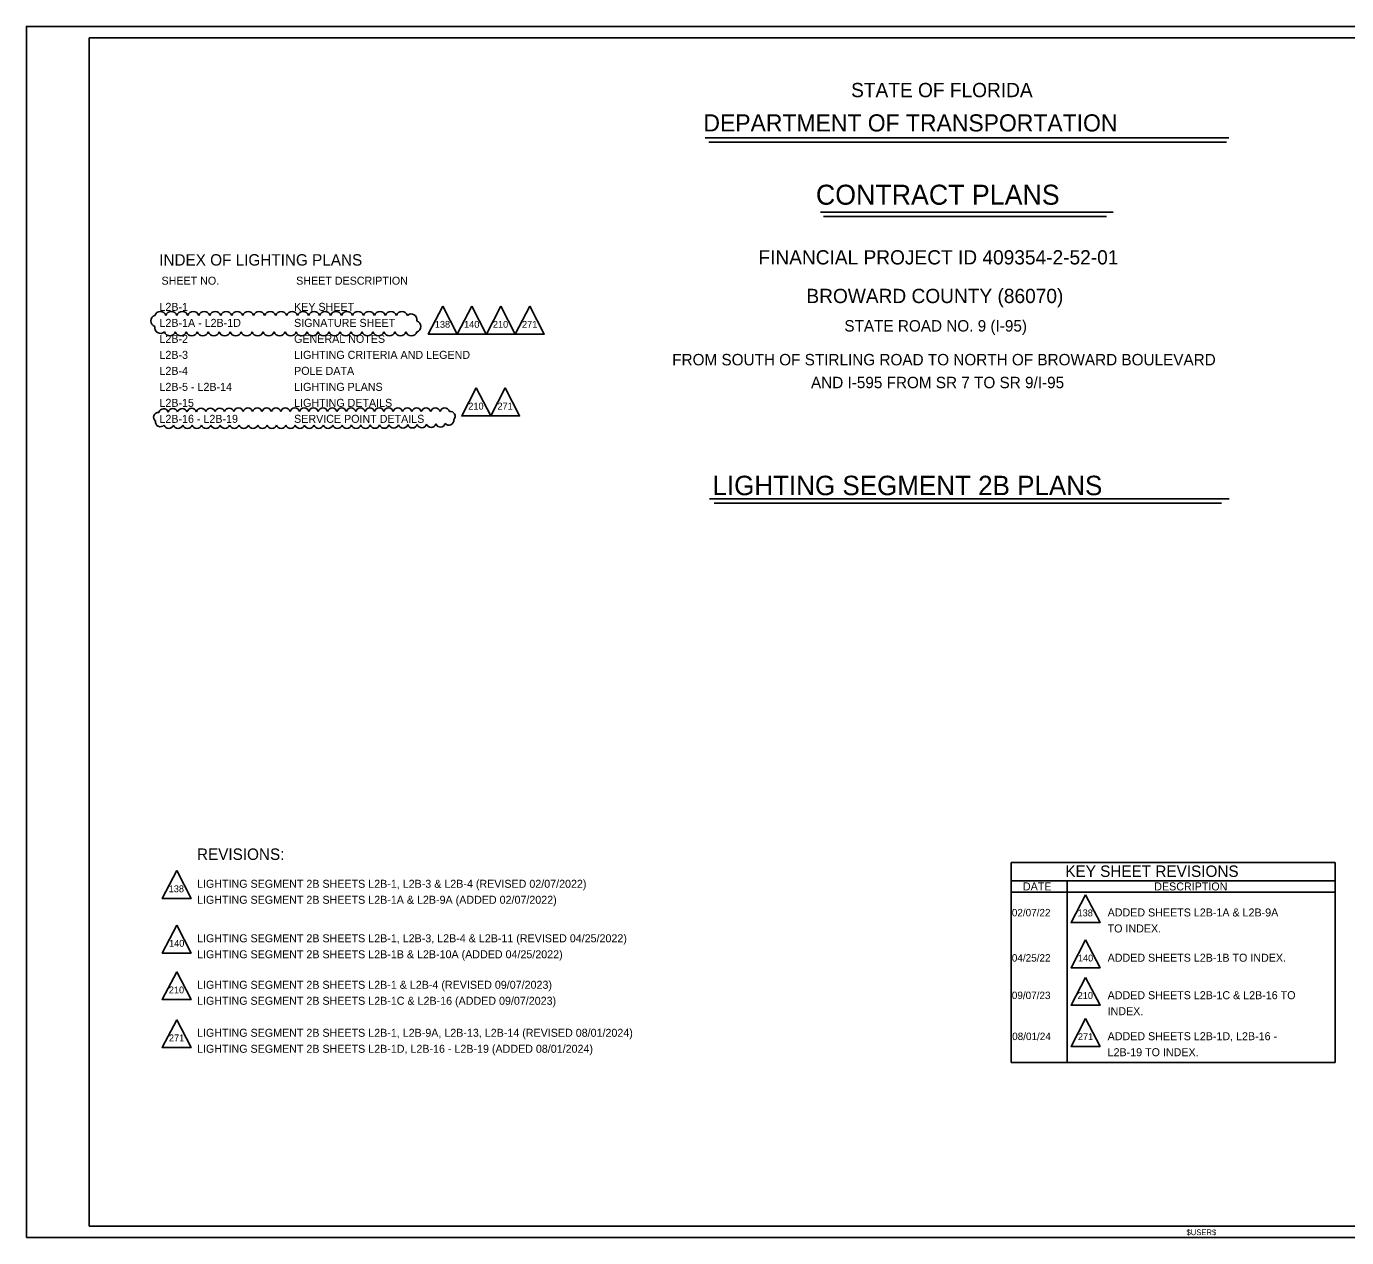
# Model space of a CAD drawing. Extents: x -820.2 to -798.1, y -2199.1 to -2188.5.
# Drawn here: x -820.23 to -808.68, y -2199.12 to -2188.52 of the extents above; entities that cross this region are included whole.
import ezdxf

# ---------------------------------------------------------------- set-up
doc = ezdxf.new("R2010")
doc.units = 0
for name, color, linetype in [('AdhocPoint_dp', 7, 'Continuous'), ('Cloud_dp', 7, 'Continuous'), ('PlotBorder_dp', 7, 'Continuous'), ('SheetBorder_dp', 7, 'Continuous'), ('SumBoxLines_dp', 7, 'Continuous'), ('TextLabel', 7, 'Continuous'), ('TextMinor', 7, 'Continuous'), ('TextNotes', 7, 'Continuous'), ('TextTitle', 7, 'Continuous')]:
    doc.layers.add(name, color=color, linetype=linetype)

msp = doc.modelspace()

# ---------------------------------------------------------------- linework, layer by layer
at = {"layer": 'AdhocPoint_dp'}
msp.add_line((-820.227, -2199.124), (-820.227, -2199.124), dxfattribs=at)
at = {"layer": 'Cloud_dp'}
for points in [[(-816.585, -2190.972), (-816.711, -2191.216), (-816.458, -2191.216)], [(-816.331, -2190.972), (-816.458, -2191.216), (-816.204, -2191.216)], [(-816.077, -2190.972), (-816.203, -2191.216), (-815.95, -2191.216)], [(-815.823, -2190.972), (-815.95, -2191.216), (-815.696, -2191.216)], [(-816.292, -2191.688), (-816.419, -2191.932), (-816.165, -2191.932)], [(-816.038, -2191.688), (-816.165, -2191.932), (-815.912, -2191.932)], [(-818.912, -2195.912), (-819.039, -2196.156), (-818.786, -2196.156)], [(-810.961, -2196.123), (-811.088, -2196.367), (-810.834, -2196.367)], [(-818.912, -2196.389), (-819.039, -2196.633), (-818.786, -2196.633)], [(-810.961, -2196.518), (-811.088, -2196.762), (-810.834, -2196.762)], [(-818.912, -2196.797), (-819.039, -2197.041), (-818.786, -2197.041)], [(-810.961, -2196.846), (-811.088, -2197.09), (-810.834, -2197.09)], [(-818.912, -2197.217), (-819.039, -2197.461), (-818.786, -2197.461)], [(-810.961, -2197.205), (-811.088, -2197.45), (-810.834, -2197.45)]]:
    msp.add_lwpolyline(points, close=True, dxfattribs=at)
for centre, radius, start, end in [((-819.088, -2191.101), 0.0504, 107.5, 252.5), ((-819.055, -2191.068), 0.0504, 17.5, 162.5), ((-818.959, -2191.068), 0.0504, 17.5, 162.5), ((-818.863, -2191.068), 0.0504, 17.5, 162.5), ((-818.767, -2191.068), 0.0504, 17.5, 162.5), ((-818.671, -2191.068), 0.0504, 17.5, 162.5), ((-818.575, -2191.068), 0.0504, 17.5, 162.5), ((-818.479, -2191.068), 0.0504, 17.5, 162.5), ((-818.383, -2191.068), 0.0504, 17.5, 162.5), ((-818.287, -2191.068), 0.0504, 17.5, 162.5), ((-818.191, -2191.068), 0.0504, 17.5, 162.5), ((-818.094, -2191.068), 0.0504, 17.5, 162.5), ((-817.998, -2191.068), 0.0504, 17.5, 162.5), ((-817.902, -2191.068), 0.0504, 17.5, 162.5), ((-817.806, -2191.068), 0.0504, 17.5, 162.5), ((-817.71, -2191.068), 0.0504, 17.5, 162.5), ((-817.614, -2191.068), 0.0504, 17.5, 162.5), ((-817.518, -2191.068), 0.0504, 17.5, 162.5), ((-817.422, -2191.068), 0.0504, 17.5, 162.5), ((-817.326, -2191.068), 0.0504, 17.5, 162.5), ((-817.23, -2191.068), 0.0504, 17.5, 162.5), ((-817.134, -2191.068), 0.0504, 17.5, 162.5), ((-817.038, -2191.068), 0.0504, 17.5, 162.5), ((-816.942, -2191.068), 0.0504, 17.5, 162.5), ((-816.86, -2191.09), 0.0503, 347.2695, 132.2695), ((-819.054, -2191.16), 0.0503, 167.2695, 312.2695), ((-816.826, -2191.15), 0.0504, 287.5, 72.5), ((-818.972, -2191.182), 0.0504, 197.5, 342.5), ((-818.876, -2191.182), 0.0504, 197.5, 342.5), ((-818.78, -2191.182), 0.0504, 197.5, 342.5), ((-818.684, -2191.182), 0.0504, 197.5, 342.5), ((-818.588, -2191.182), 0.0504, 197.5, 342.5), ((-818.492, -2191.182), 0.0504, 197.5, 342.5), ((-818.396, -2191.182), 0.0504, 197.5, 342.5), ((-818.3, -2191.182), 0.0504, 197.5, 342.5), ((-818.204, -2191.182), 0.0504, 197.5, 342.5), ((-818.108, -2191.182), 0.0504, 197.5, 342.5), ((-818.012, -2191.182), 0.0504, 197.5, 342.5), ((-817.915, -2191.182), 0.0504, 197.5, 342.5), ((-817.819, -2191.182), 0.0504, 197.5, 342.5), ((-817.723, -2191.182), 0.0504, 197.5, 342.5), ((-817.627, -2191.182), 0.0504, 197.5, 342.5), ((-817.531, -2191.182), 0.0504, 197.5, 342.5), ((-817.435, -2191.182), 0.0504, 197.5, 342.5), ((-817.339, -2191.182), 0.0504, 197.5, 342.5), ((-817.243, -2191.182), 0.0504, 197.5, 342.5), ((-817.147, -2191.182), 0.0504, 197.5, 342.5), ((-817.051, -2191.182), 0.0504, 197.5, 342.5), ((-816.955, -2191.182), 0.0504, 197.5, 342.5), ((-816.859, -2191.182), 0.0504, 197.5, 342.5), ((-819.027, -2191.913), 0.043, 19.3099, 164.3099), ((-818.945, -2191.911), 0.043, 18.5728, 163.5728), ((-818.863, -2191.91), 0.043, 18.2632, 163.2632), ((-818.781, -2191.909), 0.043, 18.0805, 163.0805), ((-818.699, -2191.908), 0.043, 17.9561, 162.9561), ((-818.617, -2191.907), 0.043, 17.8645, 162.8645), ((-818.535, -2191.907), 0.043, 17.7932, 162.7932), ((-818.453, -2191.907), 0.043, 17.7359, 162.7359), ((-818.371, -2191.906), 0.043, 17.6883, 162.6883), ((-818.289, -2191.906), 0.043, 17.6481, 162.6481), ((-818.207, -2191.906), 0.043, 17.6135, 162.6135), ((-818.125, -2191.906), 0.043, 17.5833, 162.5833), ((-818.043, -2191.906), 0.043, 17.5567, 162.5567), ((-817.961, -2191.906), 0.043, 17.533, 162.533), ((-817.879, -2191.906), 0.043, 17.5117, 162.5117), ((-817.797, -2191.906), 0.043, 17.5001, 162.5001), ((-817.715, -2191.906), 0.043, 17.5, 162.5), ((-817.633, -2191.906), 0.043, 17.5, 162.5), ((-817.551, -2191.906), 0.043, 17.5, 162.5), ((-817.469, -2191.906), 0.043, 17.5, 162.5), ((-817.387, -2191.906), 0.043, 17.5, 162.5), ((-817.305, -2191.906), 0.043, 17.5, 162.5), ((-817.223, -2191.906), 0.043, 17.5, 162.5), ((-817.141, -2191.906), 0.043, 17.5, 162.5), ((-817.059, -2191.906), 0.043, 17.5, 162.5), ((-816.977, -2191.906), 0.043, 17.5, 162.5), ((-816.895, -2191.906), 0.043, 17.5, 162.5), ((-816.813, -2191.906), 0.043, 17.5, 162.5), ((-816.731, -2191.906), 0.043, 17.5, 162.5), ((-816.649, -2191.906), 0.043, 17.5, 162.5), ((-816.567, -2191.906), 0.043, 17.5, 162.5), ((-819.071, -2191.944), 0.0429, 86.8577, 231.8577), ((-819.055, -2191.984), 0.043, 172.6222, 317.6222), ((-816.531, -2191.97), 0.043, 221.9316, 6.9316), ((-816.519, -2191.935), 0.043, 315.2071, 100.2071), ((-818.982, -2192), 0.043, 197.5, 342.5), ((-818.9, -2192), 0.043, 197.5, 342.5), ((-818.818, -2192), 0.043, 197.5, 342.5), ((-818.736, -2192), 0.043, 197.5, 342.5), ((-818.654, -2192), 0.043, 197.5, 342.5), ((-818.572, -2192), 0.043, 197.5, 342.5), ((-818.49, -2192), 0.043, 197.5, 342.5), ((-818.408, -2192), 0.043, 197.5, 342.5), ((-818.326, -2192), 0.043, 197.5, 342.5), ((-818.244, -2192), 0.043, 197.5, 342.5), ((-818.162, -2192), 0.043, 197.5, 342.5), ((-818.08, -2192), 0.043, 197.5, 342.5), ((-817.998, -2192), 0.043, 197.5, 342.5), ((-817.916, -2192), 0.043, 197.5, 342.5), ((-817.834, -2192), 0.043, 197.5, 342.5), ((-817.752, -2192), 0.043, 197.507, 342.507), ((-817.67, -2192), 0.043, 197.5411, 342.5411), ((-817.588, -2192), 0.043, 197.5814, 342.5814), ((-817.506, -2192), 0.043, 197.6265, 342.6265), ((-817.424, -2191.999), 0.043, 197.6774, 342.6774), ((-817.342, -2191.999), 0.043, 197.7355, 342.7355), ((-817.26, -2191.999), 0.043, 197.8027, 342.8027), ((-817.178, -2191.998), 0.043, 197.8816, 342.8816), ((-817.096, -2191.998), 0.043, 197.976, 342.976), ((-817.014, -2191.997), 0.043, 198.0918, 343.0918), ((-816.932, -2191.996), 0.043, 198.2386, 343.2386), ((-816.85, -2191.995), 0.043, 198.4333, 343.4333), ((-816.768, -2191.993), 0.043, 198.7095, 343.7095), ((-816.686, -2191.991), 0.043, 199.1475, 344.1475), ((-816.604, -2191.988), 0.043, 200.0205, 345.0205)]:
    msp.add_arc(centre, radius, start, end, dxfattribs=at)
at = {"layer": 'PlotBorder_dp'}
msp.add_lwpolyline([(-820.227, -2199.124), (-803.727, -2199.124), (-803.727, -2188.524), (-820.227, -2188.524)], close=True, dxfattribs=at)
at = {"layer": 'SheetBorder_dp'}
for p, q in [((-819.677, -2188.624), (-819.677, -2199.024)), ((-819.677, -2188.624), (-804.277, -2188.624)), ((-819.677, -2199.024), (-804.277, -2199.024))]:
    msp.add_line(p, q, dxfattribs=at)
at = {"layer": 'SumBoxLines_dp'}
for p, q in [((-811.612, -2195.84), (-811.612, -2197.591)), ((-811.612, -2195.84), (-808.777, -2195.84)), ((-808.777, -2195.84), (-808.777, -2197.592)), ((-811.612, -2196), (-808.777, -2196)), ((-811.122, -2196), (-811.122, -2197.591)), ((-811.612, -2196.1), (-808.777, -2196.1)), ((-811.612, -2197.591), (-808.777, -2197.591))]:
    msp.add_line(p, q, dxfattribs=at)
at = {"layer": 'TextTitle'}
for p, q in [((-814.289, -2189.5), (-809.707, -2189.5)), ((-814.257, -2189.538), (-809.729, -2189.538)), ((-813.281, -2190.15), (-810.719, -2190.15)), ((-813.253, -2190.188), (-810.777, -2190.188)), ((-814.252, -2192.659), (-809.704, -2192.659)), ((-814.209, -2192.697), (-809.772, -2192.697))]:
    msp.add_line(p, q, dxfattribs=at)

# ---------------------------------------------------------------- texts
at = {"layer": 'Cloud_dp'}
for s, p in [('138', (-816.654, -2191.161)), ('140', (-816.398, -2191.161)), ('210', (-816.146, -2191.161)), ('271', (-815.891, -2191.161)), ('210', (-816.361, -2191.877)), ('271', (-816.106, -2191.877)), ('138', (-818.982, -2196.101)), ('138', (-811.031, -2196.312)), ('140', (-818.979, -2196.578)), ('140', (-811.028, -2196.707)), ('210', (-818.981, -2196.986)), ('210', (-811.03, -2197.035)), ('271', (-818.98, -2197.406)), ('271', (-811.028, -2197.395))]:
    msp.add_text(s, height=0.06, rotation=0, dxfattribs=at).set_placement(p)
at = {"layer": 'TextLabel'}
for s, height, p in [('FINANCIAL PROJECT ID 409354-2-52-01', 0.125, (-813.823, -2190.607)), ('INDEX OF LIGHTING PLANS', 0.1, (-819.065, -2190.617)), ('BROWARD COUNTY (86070)', 0.125, (-813.403, -2190.945)), ('L2B-1', 0.07, (-819.063, -2191.013)), ('KEY SHEET', 0.07, (-817.885, -2191.013)), ('L2B-1A - L2B-1D', 0.07, (-819.063, -2191.153)), ('SIGNATURE SHEET', 0.07, (-817.885, -2191.153)), ('STATE ROAD NO. 9 (I-95)', 0.1, (-813.071, -2191.194)), ('L2B-2', 0.07, (-819.063, -2191.293)), ('GENERAL NOTES', 0.07, (-817.885, -2191.293)), ('L2B-3', 0.07, (-819.063, -2191.433)), ('LIGHTING CRITERIA AND LEGEND', 0.07, (-817.885, -2191.433)), ('FROM SOUTH OF STIRLING ROAD TO NORTH OF BROWARD BOULEVARD', 0.1, (-814.577, -2191.49)), ('L2B-4', 0.07, (-819.063, -2191.573)), ('POLE DATA', 0.07, (-817.885, -2191.573)), ('L2B-5 - L2B-14', 0.07, (-819.063, -2191.713)), ('LIGHTING PLANS', 0.07, (-817.885, -2191.713)), ('AND I-595 FROM SR 7 TO SR 9/I-95', 0.1, (-813.363, -2191.69)), ('L2B-15', 0.07, (-819.063, -2191.853)), ('LIGHTING DETAILS', 0.07, (-817.885, -2191.853)), ('L2B-16 - L2B-19', 0.07, (-819.063, -2191.993)), ('SERVICE POINT DETAILS', 0.07, (-817.885, -2191.993)), ('REVISIONS:', 0.1, (-818.735, -2195.818)), ('KEY SHEET REVISIONS', 0.1, (-811.138, -2195.967))]:
    msp.add_text(s, height=height, dxfattribs=at).set_placement(p)
at = {"layer": 'TextMinor'}
for s, height, p in [('02/07/22', 0.065, (-811.606, -2196.312)), ('ADDED SHEETS L2B-1A & L2B-9A ', 0.07, (-810.768, -2196.313)), ('TO INDEX.', 0.07, (-810.768, -2196.453)), ('04/25/22', 0.065, (-811.606, -2196.708)), ('ADDED SHEETS L2B-1B TO INDEX.', 0.07, (-810.768, -2196.709)), ('09/07/23', 0.065, (-811.606, -2197.036)), ('ADDED SHEETS L2B-1C & L2B-16 TO ', 0.07, (-810.768, -2197.037)), ('INDEX.', 0.07, (-810.768, -2197.177)), ('08/01/24', 0.065, (-811.603, -2197.395)), ('ADDED SHEETS L2B-1D, L2B-16 - ', 0.07, (-810.768, -2197.396)), ('L2B-19 TO INDEX.', 0.07, (-810.768, -2197.536)), ('$USER$', 0.05, (-810.078, -2199.102))]:
    msp.add_text(s, height=height, dxfattribs=at).set_placement(p)
at = {"layer": 'TextNotes'}
for s, height, p in [('SHEET NO.', 0.07, (-819.045, -2190.784)), ('SHEET DESCRIPTION', 0.07, (-817.867, -2190.784)), ('LIGHTING SEGMENT 2B SHEETS L2B-1, L2B-3 & L2B-4 (REVISED 02/07/2022)', 0.06998, (-818.734, -2196.062)), ('DATE', 0.07, (-811.509, -2196.085)), ('DESCRIPTION', 0.07, (-810.36, -2196.085)), ('LIGHTING SEGMENT 2B SHEETS L2B-1A & L2B-9A (ADDED 02/07/2022)', 0.06998, (-818.734, -2196.202)), ('LIGHTING SEGMENT 2B SHEETS L2B-1, L2B-3, L2B-4 & L2B-11 (REVISED 04/25/2022)', 0.06998, (-818.734, -2196.539)), ('LIGHTING SEGMENT 2B SHEETS L2B-1B & L2B-10A (ADDED 04/25/2022)', 0.06998, (-818.734, -2196.679)), ('LIGHTING SEGMENT 2B SHEETS L2B-1 & L2B-4 (REVISED 09/07/2023)', 0.06998, (-818.734, -2196.946)), ('LIGHTING SEGMENT 2B SHEETS L2B-1C & L2B-16 (ADDED 09/07/2023)', 0.06998, (-818.734, -2197.086)), ('LIGHTING SEGMENT 2B SHEETS L2B-1, L2B-9A, L2B-13, L2B-14 (REVISED 08/01/2024)', 0.06998, (-818.734, -2197.366)), ('LIGHTING SEGMENT 2B SHEETS L2B-1D, L2B-16 - L2B-19 (ADDED 08/01/2024)', 0.06998, (-818.734, -2197.506))]:
    msp.add_text(s, height=height, dxfattribs=at).set_placement(p)
at = {"layer": 'TextTitle'}
for s, height, p in [('STATE OF FLORIDA', 0.125, (-813.012, -2189.143)), ('DEPARTMENT OF TRANSPORTATION', 0.15, (-814.304, -2189.443)), ('CONTRACT PLANS', 0.175, (-813.32, -2190.084)), ('LIGHTING SEGMENT 2B PLANS', 0.17, (-814.225, -2192.626))]:
    msp.add_text(s, height=height, dxfattribs=at).set_placement(p)

doc.saveas('drawing.dxf')
